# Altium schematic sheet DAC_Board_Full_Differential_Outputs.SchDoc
size A3; SheetNumber: 0; SheetTotal: 0; PageSetup: Record=PageOptions|CenterHorizontal=True|CenterVertical=True|PrintScale=0.71|XCorrection=1.00|YCorrection=1.00|PrintKind=2|BorderSize=5000000|LeftOffset=0|BottomOffset=0|Orientation=2|PaperLength=1000|PaperWidth=1000|Scale=100|PaperSource=7|PrintQuality=-4|MediaType=1|DitherType=10|PaperKind=A4|PrintScaleMode=1
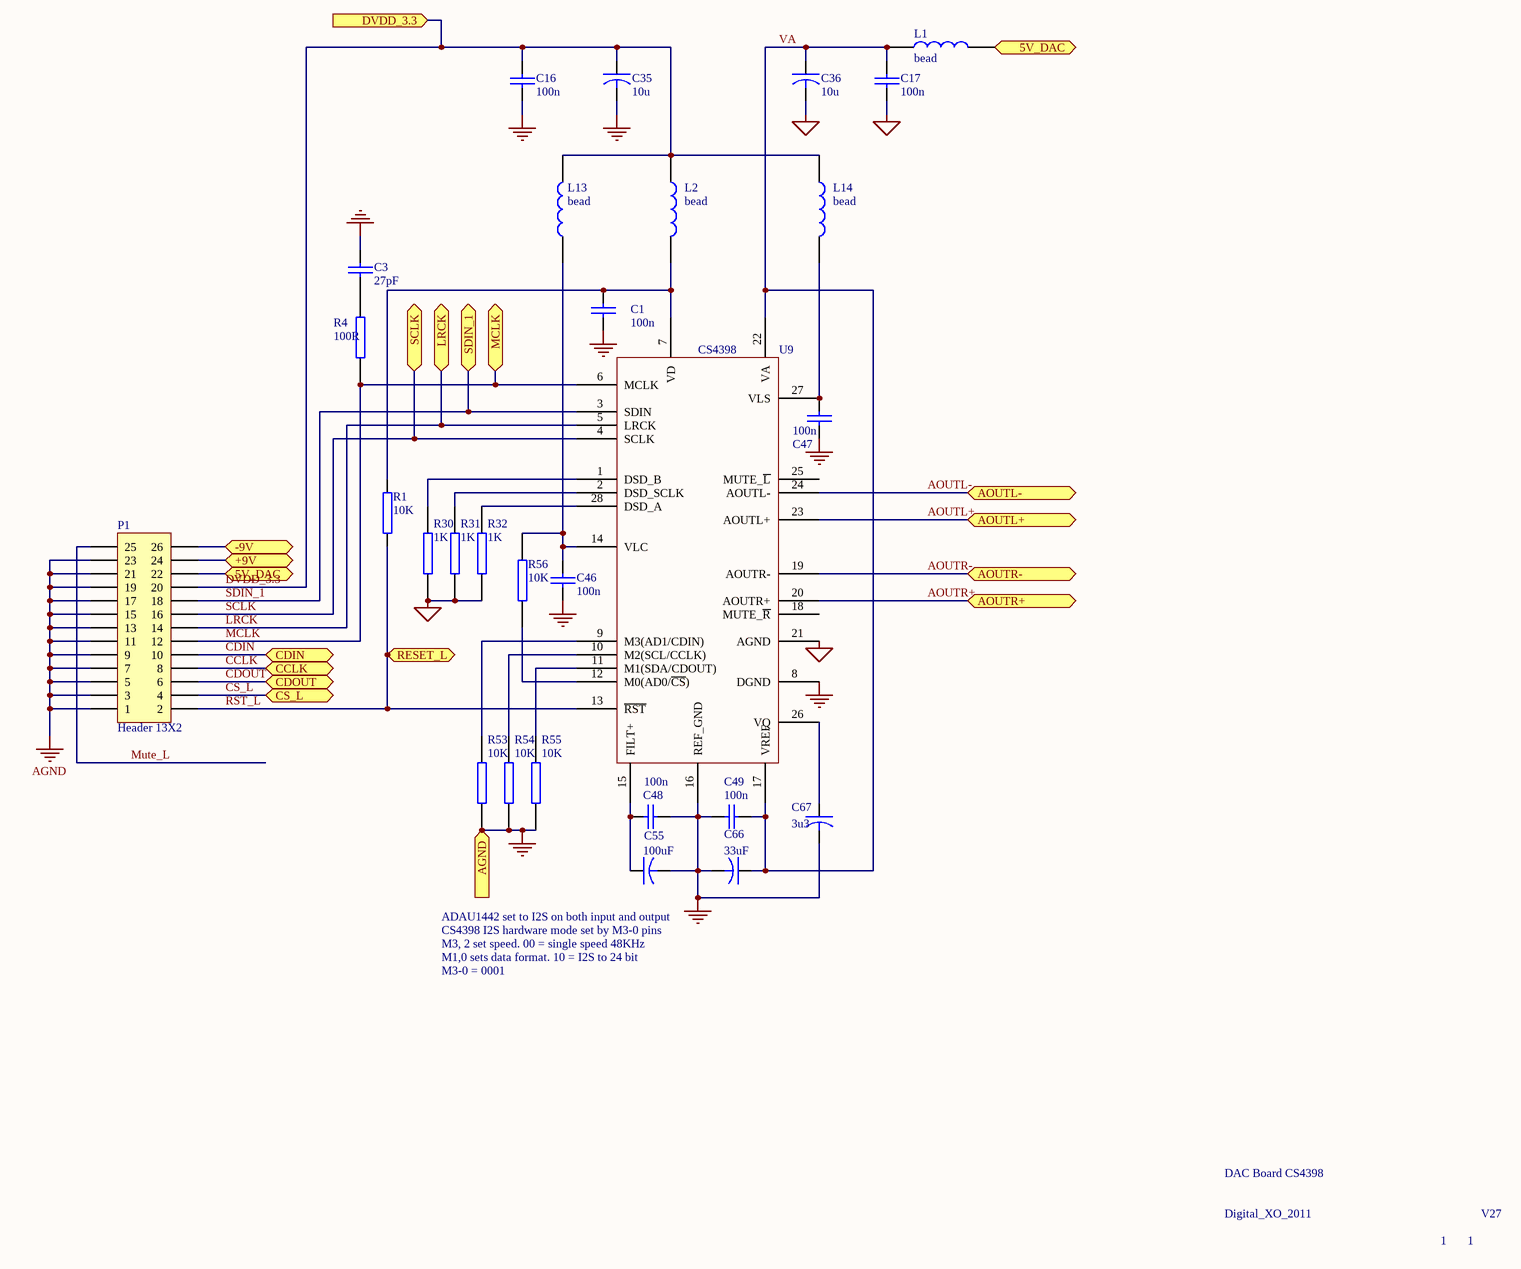
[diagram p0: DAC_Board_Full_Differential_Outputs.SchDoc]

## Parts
C1  100n  [0805]
C3  27pF  [0805]
C16  100n  [AXIAL0.2-pth]
C17  100n  [0805]
C35  10u  [RB.1/.2]
C36  10u  [RB.1/.2]
C46  100n  [0805]
C47  100n  [0805]
C48  100n  [0805]
C49  100n  [0805]
C55  100uF  [RB.1/.25-pth]
C66  33uF  [RB.1/.2]
C67  3u3  [RB.1/.2]
L1  bead  [AXIAL0.2-pth]
L2  bead  [AXIAL0.3-pth]
L13  bead  [AXIAL0.3-pth]
L14  bead  [AXIAL0.3-pth]
P1  Header 13X2  [HDR2X13]
R1  10K  [0805]
R4  100R  [0805]
R30  1K  [0805]
R31  1K  [0805]
R32  1K  [0805]
R53  10K  [0805]
R54  10K  [0805]
R55  10K  [0805]
R56  10K  [0805]
U9  CS4398  [TSSOP28]

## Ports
5V_DAC, 5V_DAC (in), +9V, -9V, AGND (in), AOUTL+, AOUTL-, AOUTR+, AOUTR-, CCLK, CDIN, CDOUT, CS_L, DVDD_3.3 (in), LRCK, MCLK, RESET_L, SCLK, SDIN_1

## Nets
AGND: C1.2 C3.2 C16.2 C17.2 C35.2 C36.2 C46.2 C47.1 C48.1 C49.1 C55.2 C66.2 C67.2 P1.1 P1.3 P1.5 P1.7 P1.9 P1.11 P1.13 P1.15 P1.17 P1.19 P1.21 P1.23 R30.1 R31.1 R32.1 R53.1 R54.1 R55.1 U9.8(DGND) U9.16(REF_GND) U9.21(AGND) ; port AGND
5V_DAC: L1.2 P1.22 ; port 5V_DAC
+9V: P1.24 ; port +9V
-9V: P1.26 ; port -9V
AOUTL+: U9.23(AOUTL+) ; port AOUTL+
AOUTL-: U9.24(AOUTL-) ; port AOUTL-
AOUTR+: U9.20(AOUTR+) ; port AOUTR+
AOUTR-: U9.19(AOUTR-) ; port AOUTR-
CCLK: P1.8 ; port CCLK
CDIN: P1.10 ; port CDIN
CDOUT: P1.6 ; port CDOUT
CS_L: P1.4 ; port CS_L
DVDD_3.3: C16.1 C35.1 L2.1 L13.2 L14.1 P1.20 ; port DVDD_3.3
LRCK: P1.14 U9.5(LRCK) ; port LRCK
MCLK: P1.12 R4.1 U9.6(MCLK) ; port MCLK
Mute_L: P1.25
RST_L: P1.2 R1.1 U9.13(~{RST}) ; port RESET_L
SCLK: P1.16 U9.4(SCLK) ; port SCLK
SDIN_1: P1.18 U9.3(SDIN) ; port SDIN_1
VA: C17.1 C36.1 C49.2 C66.1 L1.1 U9.17(VREF) U9.22(VA)
NetC1_1: C1.1 L2.2 R1.2 U9.7(VD)
NetC3_1: C3.1 R4.2
NetC46_1: C46.1 L13.1 R56.1 U9.14(VLC)
NetC47_2: C47.2 L14.2 U9.27(VLS)
NetC48_2: C48.2 C55.1 U9.15(FILT+)
NetC67_1: C67.1 U9.26(VQ)
NetR30_2: R30.2 U9.1(DSD_B)
NetR31_2: R31.2 U9.2(DSD_SCLK)
NetR32_2: R32.2 U9.28(DSD_A)
NetR53_2: R53.2 U9.9(M3(AD1/CDIN))
NetR54_2: R54.2 U9.10(M2(SCL/CCLK))
NetR55_2: R55.2 U9.11(M1(SDA/CDOUT))
NetR56_2: R56.2 U9.12(M0(AD0/~{CS}))

Not connected (* = marked no-connect by the designer): U9 18(MUTE_~{R}) 25(MUTE_~{L})

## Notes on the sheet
- ADAU1442 set to I2S on both input and output
- CS4398 I2S hardware mode set by M3-0 pins
- M3, 2 set speed. 00 = single speed 48KHz
- M1,0 sets data format. 10 = I2S to 24 bit
- M3-0 = 0001
- DAC Board CS4398
- Digital_XO_2011
- 1
- V27

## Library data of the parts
C1 C46-C49 = CAP
C3 C16 C17 = CAP: Capacitor
C35 C36 C55 C66 C67 = CAPACITOR
L1 L2 L13 L14 = INDUCTOR1
P1 = Header 13X2: Header, 13-Pin, Dual row
R1 R4 R30-R32 R53-R56 = RES2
